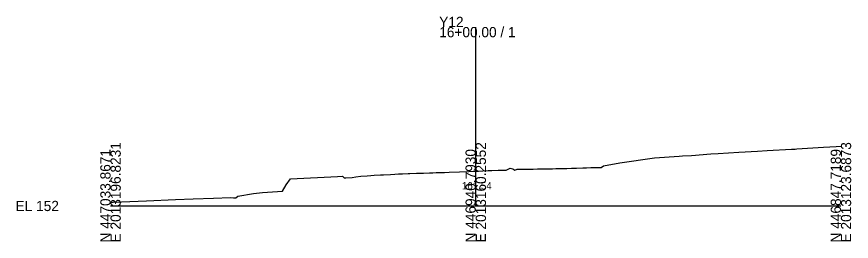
# Model space of a CAD drawing. Extents: x -26 to 1203, y -10 to 9542.
# Drawn here: x 974.3 to 1202.8, y 1990.3 to 2051.9 of the extents above; entities that cross this region are included whole.
import ezdxf

# ---------------------------------------------------------------- set-up
doc = ezdxf.new("R2010")
doc.units = 0
for name, color, linetype in [('Default', 7, 'Continuous'), ('Exist Cross Section Cell', 7, 'Continuous'), ('Exist XS Center Line Elevation Label', 7, 'Continuous'), ('Exist XS Ground Line', 7, 'Continuous')]:
    doc.layers.add(name, color=color, linetype=linetype)

msp = doc.modelspace()

# ---------------------------------------------------------------- linework, layer by layer
at = {"layer": 'Exist Cross Section Cell'}
for p, q in [((1100, 2000), (1100, 2049.04)), ((1000, 2000), (1100, 2000)), ((1100, 2000), (1200, 2000))]:
    msp.add_line(p, q, dxfattribs=at)
at = {"layer": 'Exist XS Ground Line'}
msp.add_lwpolyline([(1000, 2000.99), (1000.73, 2001.02), (1009.83, 2001.39), (1017.82, 2001.76), (1022.62, 2001.96), (1028.24, 2002.12), (1032.85, 2002.31), (1033.68, 2002.26), (1034.35, 2002.21), (1034.85, 2002.71), (1039.11, 2003.43), (1041.57, 2003.66), (1047.05, 2004.07), (1048.12, 2005.79), (1049.26, 2007.4), (1062.19, 2008.03), (1063.48, 2008.21), (1064.02, 2007.72), (1064.47, 2007.74), (1066.17, 2007.83), (1067.13, 2007.96), (1068.57, 2008.18), (1070.28, 2008.29), (1071.25, 2008.35), (1072.22, 2008.41), (1073.93, 2008.5), (1074.72, 2008.55), (1076.63, 2008.66), (1077.85, 2008.73), (1078.82, 2008.76), (1079.31, 2008.78), (1079.93, 2008.81), (1081.49, 2008.87), (1082, 2008.89), (1083.78, 2008.95), (1084.67, 2008.98), (1085.7, 2009.01), (1087.34, 2009.07), (1088.29, 2009.11), (1089.16, 2009.13), (1090.02, 2009.16), (1091.47, 2009.2), (1092.71, 2009.24), (1095.54, 2009.34), (1098.08, 2009.45), (1099.77, 2009.53), (1100.75, 2009.57), (1101.94, 2009.62), (1103.42, 2009.68), (1104.43, 2009.71), (1106.12, 2009.77), (1108.31, 2009.85), (1108.86, 2010.06), (1109.46, 2010.36), (1110.14, 2010.15), (1110.74, 2009.85), (1111.36, 2010.04), (1111.68, 2010.04), (1113.37, 2010.07), (1114.24, 2010.08), (1114.66, 2010.09), (1115.71, 2010.11), (1116.93, 2010.14), (1117.71, 2010.15), (1119.59, 2010.18), (1121.03, 2010.21), (1121.92, 2010.23), (1122.52, 2010.24), (1124.25, 2010.29), (1124.93, 2010.31), (1126.18, 2010.34), (1127.62, 2010.38), (1129.34, 2010.43), (1130.3, 2010.46), (1131.52, 2010.5), (1132.55, 2010.54), (1133.87, 2010.55), (1134.39, 2010.56), (1135.03, 2010.98), (1139.49, 2011.78), (1148.92, 2013.22), (1155.67, 2013.63), (1156.64, 2013.72), (1159.09, 2013.86), (1164.35, 2014.25), (1166.42, 2014.34), (1172.07, 2014.77), (1177.16, 2015.06), (1179.78, 2015.16), (1186.44, 2015.55), (1187.49, 2015.61), (1187.91, 2015.63), (1195.21, 2016.1), (1198.65, 2016.29), (1200, 2016.35)], dxfattribs=at)

# ---------------------------------------------------------------- texts
at = {"layer": 'Default'}
msp.add_text('-', height=0.0001, dxfattribs=at).set_placement((1000, 2000))
at = {"layer": 'Exist Cross Section Cell'}
for s, p in [('Y12', (1090, 2049.04)), ('16+00.00 / 1', (1090, 2046.24)), ('EL 152', (974, 1998.6))]:
    msp.add_text(s, height=2.8, dxfattribs=at).set_placement(p)
for s, p in [('E 2013196.8231', (1002.8, 1990)), ('E 2013160.2552', (1102.8, 1990)), ('E 2013123.6873', (1202.8, 1990)), ('N 447033.8671', (1000, 1990)), ('N 446940.7930', (1100, 1990)), ('N 446847.7189', (1200, 1990))]:
    msp.add_text(s, height=2.8, rotation=90, dxfattribs=at).set_placement(p)
at = {"layer": 'Exist XS Center Line Elevation Label'}
msp.add_text('161.54', height=2, dxfattribs=at).set_placement((1096.2, 2004.54))

doc.saveas('drawing.dxf')
